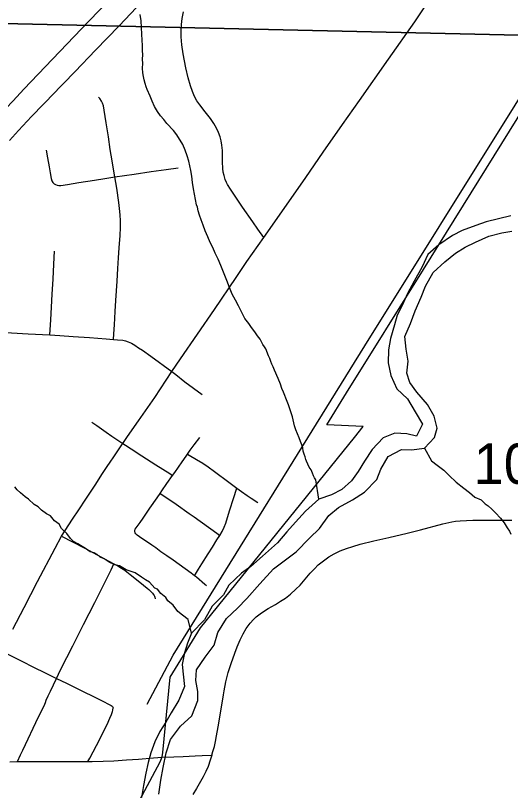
# Model space of a CAD drawing. Extents: x -8.8 to 41.4, y 0 to 34.6.
# Drawn here: x 2.435 to 2.947, y 16.815 to 17.616 of the extents above; entities that cross this region are included whole.
import ezdxf

# ---------------------------------------------------------------- set-up
doc = ezdxf.new("R2010")
doc.units = 0
for name, color, linetype in [('GM_X_City_Street', 7, 'Continuous'), ('GM_X_Corporation', 7, 'Continuous'), ('GM_X_County_Road', 7, 'Continuous'), ('GM_X_Major_Lake', 7, 'Continuous'), ('GM_X_Minor_River', 7, 'Continuous'), ('GM_X_Rail_Line', 7, 'Continuous'), ('GM_X_State_Route', 7, 'Continuous'), ('GM_X_Township_Text', 7, 'Continuous'), ('GM_X_US_Route', 7, 'Continuous')]:
    doc.layers.add(name, color=color, linetype=linetype)

msp = doc.modelspace()

# ---------------------------------------------------------------- linework, layer by layer
at = {"layer": 'GM_X_City_Street'}
for points in [[(2.43223, 16.98123), (2.4438, 17.00368), (2.45783, 17.03052), (2.47584, 17.06495), (2.48261, 17.0774), (2.49387, 17.09493), (2.50055, 17.10482), (2.50774, 17.11569), (2.51726, 17.13021), (2.52499, 17.14224), (2.52914, 17.14842), (2.5337, 17.15504), (2.53611, 17.15862), (2.53809, 17.16174), (2.54089, 17.16579), (2.54494, 17.17197), (2.54595, 17.17337), (2.54816, 17.17644), (2.55024, 17.17943), (2.5508, 17.18043), (2.56211, 17.19658), (2.57904, 17.22103), (2.59669, 17.2476), (2.60574, 17.26074), (2.64088, 17.31199), (2.66315, 17.34492), (2.67425, 17.36144), (2.69166, 17.38626), (2.7103, 17.41282), (2.73518, 17.44849), (2.75313, 17.47461), (2.77317, 17.50307), (2.79078, 17.5279), (2.82074, 17.57065), (2.84787, 17.6093), (2.85883, 17.62586)], [(2.69166, 17.38626), (2.68573, 17.39483), (2.68044, 17.40249), (2.66979, 17.41779), (2.66057, 17.43106), (2.6572, 17.43628), (2.65434, 17.44107), (2.65321, 17.44328), (2.65194, 17.4461), (2.65061, 17.45023), (2.64981, 17.45386), (2.64934, 17.45756), (2.64904, 17.46439), (2.64889, 17.47619), (2.64844, 17.48177), (2.64774, 17.48606), (2.64667, 17.49027), (2.645, 17.49495), (2.64289, 17.49945), (2.6401, 17.5043), (2.63661, 17.50944), (2.63126, 17.5163), (2.62546, 17.52361), (2.62265, 17.5277), (2.6202, 17.53202), (2.6179, 17.53711), (2.61587, 17.54298), (2.61356, 17.55137), (2.61123, 17.56167), (2.60835, 17.57631), (2.60704, 17.58554), (2.60632, 17.59359), (2.60615, 17.60042), (2.60648, 17.60662), (2.60725, 17.61278), (2.60854, 17.6195)], [(2.5364, 17.28088), (2.5367, 17.28674), (2.53718, 17.29602), (2.53807, 17.30965), (2.53883, 17.32129), (2.54012, 17.34117), (2.54083, 17.35415), (2.54155, 17.3654), (2.5422, 17.37546), (2.54304, 17.38843), (2.54352, 17.39656), (2.54359, 17.40344), (2.54325, 17.40956), (2.54255, 17.41644), (2.54166, 17.42246), (2.53962, 17.43719), (2.5377, 17.44906), (2.53395, 17.47125), (2.53297, 17.47736), (2.53108, 17.49022), (2.53047, 17.49445), (2.52883, 17.50482), (2.52667, 17.51797), (2.52584, 17.52239), (2.52506, 17.52504), (2.52405, 17.52715), (2.52203, 17.53008), (2.52088, 17.53136)], [(2.46677, 17.47671), (2.46818, 17.46857), (2.46976, 17.45952), (2.47085, 17.45325), (2.4719, 17.44722), (2.47263, 17.44486), (2.47355, 17.44327), (2.47481, 17.44192), (2.47639, 17.44099), (2.47813, 17.44043), (2.47992, 17.44016), (2.48173, 17.44016), (2.48881, 17.44108), (2.50045, 17.44313), (2.51663, 17.44566), (2.52723, 17.44737), (2.5377, 17.44906), (2.5577, 17.4519), (2.57527, 17.45441), (2.59069, 17.4566), (2.6033, 17.4584)], [(2.47057, 17.2855), (2.47142, 17.30121), (2.47236, 17.31419), (2.47305, 17.32782), (2.47393, 17.34328), (2.4747, 17.3586), (2.47538, 17.37231)], [(2.41961, 17.28827), (2.44798, 17.28673), (2.47057, 17.2855), (2.48084, 17.28491), (2.49466, 17.28386), (2.51139, 17.28282), (2.52874, 17.28147), (2.5364, 17.28088), (2.54061, 17.28063), (2.54583, 17.28003), (2.54873, 17.27942), (2.55141, 17.27858), (2.5548, 17.27712), (2.55832, 17.27506), (2.56227, 17.27238), (2.56619, 17.26972), (2.57474, 17.26374), (2.59669, 17.2476), (2.60061, 17.24471), (2.60998, 17.23707), (2.62816, 17.22401)], [(2.51374, 17.19554), (2.51916, 17.19176), (2.52881, 17.185), (2.53472, 17.18104), (2.54595, 17.17337), (2.54879, 17.17155), (2.55474, 17.16772), (2.56567, 17.1607), (2.58021, 17.15136), (2.5945, 17.14218), (2.59744, 17.14029)], [(2.63246, 17.02607), (2.63059, 17.02769), (2.62213, 17.03498), (2.62004, 17.03662), (2.61677, 17.0392), (2.59809, 17.05255), (2.5915, 17.0572), (2.58539, 17.06145), (2.57993, 17.06547), (2.5759, 17.06836), (2.56318, 17.07686), (2.56061, 17.07862), (2.55931, 17.07996), (2.55869, 17.08101), (2.55838, 17.08219), (2.55841, 17.08342), (2.55874, 17.08461), (2.55961, 17.08626), (2.56371, 17.09174), (2.567, 17.09626), (2.57396, 17.10654), (2.58129, 17.11711), (2.58447, 17.12179), (2.58614, 17.12423), (2.59143, 17.13186), (2.59744, 17.14029), (2.59972, 17.1435), (2.60714, 17.15422), (2.61141, 17.16029), (2.61286, 17.1624), (2.61568, 17.16637), (2.61955, 17.1718), (2.62542, 17.17964)], [(2.61286, 17.1624), (2.61463, 17.16134), (2.62221, 17.1568), (2.62856, 17.15295), (2.63418, 17.14909), (2.64075, 17.14444), (2.65567, 17.13343), (2.66397, 17.12699), (2.66852, 17.12383), (2.67465, 17.11957), (2.67872, 17.11674), (2.68539, 17.11229)], [(2.62004, 17.03662), (2.62429, 17.0434), (2.62778, 17.04899), (2.63412, 17.05911), (2.63855, 17.06621), (2.64331, 17.0738), (2.64615, 17.07835), (2.64862, 17.08242), (2.65087, 17.08683), (2.65249, 17.09086), (2.65412, 17.09684), (2.65646, 17.10483), (2.66026, 17.11634), (2.66397, 17.12699)], [(2.58447, 17.12179), (2.58822, 17.11922), (2.60095, 17.1105), (2.61459, 17.10097), (2.61968, 17.09748), (2.64329, 17.0805), (2.64615, 17.07835)], [(2.48261, 17.0774), (2.49377, 17.07162), (2.50656, 17.06498), (2.51503, 17.06057), (2.52387, 17.05592), (2.53094, 17.05213), (2.53673, 17.04903), (2.54093, 17.04673), (2.54448, 17.04455), (2.5479, 17.04221), (2.55019, 17.04051), (2.55366, 17.03792), (2.56363, 17.03004), (2.57125, 17.02382), (2.57274, 17.02247), (2.57481, 17.0204), (2.5765, 17.01867), (2.57742, 17.01754), (2.57821, 17.0163), (2.57867, 17.0154), (2.57899, 17.01444), (2.57932, 17.01278)], [(2.437, 16.84438), (2.44012, 16.85133), (2.44241, 16.85643), (2.45865, 16.89065), (2.46448, 16.90227), (2.46591, 16.90567), (2.46681, 16.90794), (2.46883, 16.91244), (2.47122, 16.91743), (2.47739, 16.93051), (2.48149, 16.93919), (2.48788, 16.95193), (2.49424, 16.964), (2.50524, 16.98628), (2.51692, 17.00892), (2.52576, 17.02603), (2.53378, 17.04285), (2.53673, 17.04903)], [(2.42092, 16.95841), (2.42759, 16.9551), (2.43593, 16.95097), (2.44279, 16.94757), (2.45218, 16.94294), (2.46709, 16.93558), (2.47739, 16.93051), (2.48775, 16.9254), (2.50349, 16.91763), (2.51701, 16.91094), (2.52458, 16.9072), (2.53263, 16.90312), (2.53386, 16.90241), (2.53478, 16.90177), (2.53528, 16.90127), (2.53598, 16.9)], [(2.50988, 16.84448), (2.51168, 16.84789), (2.51857, 16.86102), (2.52963, 16.88294), (2.5324, 16.88926), (2.53414, 16.89325), (2.53533, 16.89624), (2.53577, 16.89759), (2.53598, 16.9)]]:
    msp.add_lwpolyline(points, dxfattribs=at)
at = {"layer": 'GM_X_Corporation'}
for points in [[(2.36341, 18.68599), (3.3405, 18.67291), (3.35337, 18.6726), (3.33653, 17.58688), (2.37595, 17.60863)], [(2.37595, 17.60863), (3.33653, 17.58688), (3.32694, 16.59683), (2.35425, 16.60371)]]:
    msp.add_lwpolyline(points, close=True, dxfattribs=at)
for points in [[(2.55005, 16.77968), (2.58441, 16.84415), (2.58647, 16.84942), (2.5874, 16.85382), (2.59486, 16.93175), (2.62635, 16.98275), (2.78545, 17.17966), (2.7946, 17.19099), (2.75682, 17.19274), (2.77742, 17.22583), (2.85675, 17.3532), (3.0111, 17.60104), (3.28055, 18.03435)], [(2.58363, 17.64937), (2.54201, 17.60513), (2.51786, 17.58008), (2.49655, 17.55785), (2.47175, 17.53225), (2.46757, 17.52791), (2.46379, 17.52398), (2.45161, 17.51135), (2.43813, 17.49706), (2.42871, 17.48664)]]:
    msp.add_lwpolyline(points, dxfattribs=at)
at = {"layer": 'GM_X_County_Road'}
for p, q in [((2.42901, 16.84437), (2.437, 16.84438)), ((2.50583, 16.84447), (2.50988, 16.84448))]:
    msp.add_line(p, q, dxfattribs=at)
for points in [[(2.58671, 16.84889), (2.59874, 16.84945), (2.60847, 16.84989), (2.62071, 16.85045), (2.62811, 16.8508), (2.63787, 16.85124)], [(2.63787, 16.85124), (2.63637, 16.84604), (2.6341, 16.83931), (2.63188, 16.83417), (2.62916, 16.82886), (2.62209, 16.81658), (2.61838, 16.81032)], [(2.437, 16.84438), (2.44547, 16.84439), (2.46033, 16.84441), (2.48199, 16.84444), (2.50178, 16.84446), (2.50583, 16.84447)], [(2.50988, 16.84448), (2.51434, 16.84448), (2.52564, 16.84494), (2.53661, 16.84539), (2.54986, 16.84627), (2.56228, 16.84709), (2.57765, 16.84822), (2.58671, 16.84889)]]:
    msp.add_lwpolyline(points, dxfattribs=at)
at = {"layer": 'GM_X_Major_Lake'}
for points in [[(2.94702, 17.40861), (2.9218, 17.40255), (2.91106, 17.39871), (2.89686, 17.39345), (2.88685, 17.38844), (2.87289, 17.37862), (2.86121, 17.36873), (2.85551, 17.35599), (2.84708, 17.34106), (2.84024, 17.32836), (2.83493, 17.31599), (2.82969, 17.3059), (2.82673, 17.29612), (2.82288, 17.28181), (2.82062, 17.27011), (2.82021, 17.25683), (2.82321, 17.24345), (2.82924, 17.22997), (2.84029, 17.21938), (2.84823, 17.20622), (2.8558, 17.19346), (2.84972, 17.18074), (2.83956, 17.18333), (2.82707, 17.18409), (2.81516, 17.17914), (2.80378, 17.16696), (2.79583, 17.15506), (2.78943, 17.14424), (2.7823, 17.13459), (2.77255, 17.12578), (2.76176, 17.12041), (2.74873, 17.11588), (2.73469, 17.1034), (2.72448, 17.09194), (2.71545, 17.08197), (2.70599, 17.07049), (2.6904, 17.05692), (2.67831, 17.04628), (2.66862, 17.03936), (2.65572, 17.02685), (2.6501, 17.01677), (2.63835, 17.00498), (2.63034, 16.99118), (2.61702, 16.97716), (2.61291, 16.96703), (2.60956, 16.95688), (2.60729, 16.94481), (2.6085, 16.93489), (2.60962, 16.92195), (2.60388, 16.90808), (2.5959, 16.89503), (2.59029, 16.88533), (2.5843, 16.87564), (2.57903, 16.86479), (2.57489, 16.85353), (2.5723, 16.84336), (2.56969, 16.83242), (2.5674, 16.81958), (2.56513, 16.8075)], [(2.58306, 16.81075), (2.5854, 16.8251), (2.5877, 16.83833), (2.59082, 16.85342), (2.59542, 16.86733), (2.60571, 16.88106), (2.61741, 16.89171), (2.62359, 16.90747), (2.6235, 16.91696), (2.62158, 16.92842), (2.6223, 16.93941), (2.63104, 16.95243), (2.64052, 16.96467), (2.64434, 16.97784), (2.65313, 16.99238), (2.66446, 17.00304), (2.67425, 17.01299), (2.68761, 17.02815), (2.70175, 17.04366), (2.71263, 17.05206), (2.72504, 17.06117), (2.73914, 17.07554), (2.74931, 17.08548), (2.75882, 17.09886), (2.76895, 17.10728), (2.7836, 17.11519), (2.79598, 17.12316), (2.80852, 17.13606), (2.81265, 17.14695), (2.82026, 17.16), (2.83413, 17.16717), (2.84436, 17.16685), (2.85806, 17.16833), (2.86826, 17.17941), (2.87084, 17.1892), (2.86781, 17.20145), (2.86098, 17.21381), (2.84999, 17.2263), (2.84271, 17.23639), (2.8396, 17.24598), (2.84112, 17.25847), (2.83884, 17.27069), (2.83774, 17.28401), (2.84346, 17.29751), (2.84842, 17.31064), (2.85453, 17.3245), (2.85906, 17.33614), (2.8667, 17.34995), (2.8788, 17.36097), (2.89008, 17.37012), (2.90013, 17.37626), (2.91053, 17.38163), (2.92437, 17.38767), (2.93775, 17.39105), (2.94805, 17.39301)]]:
    msp.add_lwpolyline(points, dxfattribs=at)
at = {"layer": 'GM_X_Minor_River'}
for points in [[(2.74873, 17.11588), (2.74548, 17.13564), (2.74405, 17.13798), (2.74299, 17.13992), (2.74195, 17.14262), (2.74057, 17.1461), (2.73878, 17.14882), (2.73599, 17.15502), (2.73531, 17.15694), (2.73465, 17.15963), (2.73362, 17.16233), (2.7326, 17.16541), (2.73198, 17.16886), (2.73096, 17.17194), (2.72958, 17.17541), (2.72822, 17.17927), (2.72647, 17.18314), (2.72474, 17.18738), (2.72339, 17.19162), (2.72148, 17.20081), (2.71878, 17.20928), (2.71741, 17.21314), (2.71465, 17.22009), (2.71361, 17.22279), (2.71223, 17.22626), (2.71049, 17.23013), (2.70915, 17.23474), (2.70672, 17.24054), (2.70288, 17.24905), (2.7015, 17.25253), (2.70009, 17.25524), (2.69906, 17.25795), (2.69804, 17.26103), (2.69664, 17.26412), (2.69388, 17.27107), (2.69245, 17.27341), (2.69065, 17.27576), (2.68924, 17.27848), (2.68782, 17.28119), (2.6853, 17.28471), (2.68242, 17.28863), (2.67918, 17.29331), (2.6763, 17.29723), (2.6734, 17.30076), (2.67196, 17.30272), (2.66986, 17.30736), (2.6681, 17.31085), (2.66563, 17.31551), (2.66244, 17.32134), (2.65889, 17.32756), (2.65612, 17.33451), (2.65338, 17.34184), (2.64715, 17.35729), (2.64437, 17.36385), (2.64158, 17.37005), (2.63915, 17.37584), (2.63633, 17.38128), (2.6339, 17.38707), (2.63111, 17.39326), (2.62906, 17.39904), (2.62699, 17.40445), (2.62529, 17.40946), (2.62394, 17.41369), (2.62334, 17.41751), (2.6223, 17.42021), (2.62007, 17.43094), (2.61916, 17.43668), (2.6179, 17.44319), (2.6174, 17.44967), (2.61611, 17.45542), (2.61423, 17.46538), (2.61255, 17.47076), (2.6105, 17.47655), (2.60807, 17.48234), (2.60163, 17.49248), (2.59838, 17.49679), (2.59146, 17.50428), (2.58819, 17.50821), (2.58493, 17.51214), (2.58168, 17.51645), (2.57886, 17.52188), (2.57641, 17.5273), (2.57433, 17.53232), (2.57119, 17.53928), (2.57016, 17.54199), (2.56916, 17.54545), (2.56817, 17.54928), (2.56717, 17.55274), (2.56656, 17.55657), (2.56638, 17.56152), (2.56656, 17.56607), (2.56637, 17.57064), (2.56655, 17.57519), (2.56635, 17.57976), (2.56617, 17.58471), (2.56602, 17.59041), (2.5655, 17.59651), (2.5654, 17.60336), (2.56492, 17.61022), (2.56403, 17.61671)], [(2.85806, 17.16833), (2.86531, 17.15552), (2.87085, 17.15077), (2.87789, 17.14558), (2.8834, 17.14007), (2.89077, 17.13335), (2.89853, 17.12701), (2.90446, 17.12262), (2.90999, 17.11787), (2.91636, 17.11499), (2.92078, 17.11103), (2.92375, 17.10903), (2.92743, 17.10548), (2.93148, 17.10154), (2.9366, 17.09604), (2.94024, 17.09135), (2.94349, 17.0863), (2.94564, 17.08281), (2.94706, 17.07972)], [(2.61702, 16.97716), (2.61351, 16.99143), (2.60758, 16.99581), (2.60277, 16.99978), (2.59805, 17.00602), (2.59251, 17.01078), (2.59036, 17.01427), (2.58517, 17.01825), (2.5819, 17.02255), (2.5789, 17.02379), (2.57342, 17.03006), (2.56932, 17.03248), (2.56524, 17.03528), (2.55855, 17.0397), (2.55441, 17.04098), (2.54953, 17.04267), (2.54245, 17.04672), (2.53755, 17.04803), (2.53193, 17.0505), (2.52674, 17.0541), (2.52261, 17.05577), (2.51929, 17.05854), (2.51631, 17.06017), (2.51217, 17.06145), (2.50734, 17.06466), (2.50399, 17.06668), (2.49952, 17.06949), (2.49505, 17.07193), (2.49174, 17.07508), (2.48811, 17.08015), (2.48259, 17.08528), (2.48009, 17.08993), (2.47527, 17.09352), (2.47127, 17.0986), (2.46716, 17.10064), (2.46196, 17.10424), (2.45828, 17.10779), (2.45419, 17.11021), (2.4483, 17.11574), (2.44496, 17.11813), (2.44017, 17.12248), (2.43685, 17.12525), (2.43429, 17.12838)]]:
    msp.add_lwpolyline(points, dxfattribs=at)
at = {"layer": 'GM_X_Rail_Line'}
msp.add_lwpolyline([(2.57116, 16.90399), (2.59813, 16.95461), (2.79608, 17.27414), (3.10727, 17.77216), (3.34288, 18.15157), (3.39796, 18.23981), (3.43473, 18.29166)], dxfattribs=at)
at = {"layer": 'GM_X_State_Route'}
for p, q in [((2.42901, 16.84437), (2.437, 16.84438)), ((2.50583, 16.84447), (2.50988, 16.84448))]:
    msp.add_line(p, q, dxfattribs=at)
for points in [[(2.63787, 16.85124), (2.63911, 16.85486), (2.64059, 16.86006), (2.64183, 16.86538), (2.64296, 16.87092), (2.64459, 16.88024), (2.64825, 16.90291), (2.64989, 16.91333), (2.65066, 16.9176), (2.65255, 16.92676), (2.65498, 16.93644), (2.65792, 16.94598), (2.66162, 16.95658), (2.66412, 16.96297), (2.66735, 16.97043), (2.67047, 16.97658), (2.67366, 16.98199), (2.67775, 16.98758), (2.68115, 16.99132), (2.68386, 16.99397), (2.68927, 16.99828), (2.69609, 17.00278), (2.70371, 17.00703), (2.70901, 17.0102), (2.71416, 17.01356), (2.71951, 17.01767), (2.72497, 17.02264), (2.72928, 17.02702), (2.73981, 17.03923), (2.74402, 17.04384), (2.74808, 17.04777), (2.75344, 17.05213), (2.75914, 17.05603), (2.76457, 17.05919), (2.77076, 17.06224), (2.77716, 17.06481), (2.78368, 17.067), (2.79151, 17.06919), (2.80542, 17.07254), (2.82116, 17.07614), (2.83988, 17.08048), (2.85367, 17.08395), (2.87702, 17.09022), (2.88613, 17.09227), (2.88984, 17.09291), (2.89482, 17.09352), (2.9079, 17.09404), (2.92095, 17.09401), (2.93027, 17.09402), (2.93959, 17.09394), (2.94829, 17.09391)], [(2.58671, 16.84889), (2.59874, 16.84945), (2.60847, 16.84989), (2.62071, 16.85045), (2.62811, 16.8508), (2.63787, 16.85124)], [(2.437, 16.84438), (2.44547, 16.84439), (2.46033, 16.84441), (2.48199, 16.84444), (2.50178, 16.84446), (2.50583, 16.84447)], [(2.50988, 16.84448), (2.51434, 16.84448), (2.52564, 16.84494), (2.53661, 16.84539), (2.54986, 16.84627), (2.56228, 16.84709), (2.57765, 16.84822), (2.58671, 16.84889)]]:
    msp.add_lwpolyline(points, dxfattribs=at)
at = {"layer": 'GM_X_US_Route'}
msp.add_lwpolyline([(2.30105, 17.35359), (2.30769, 17.36469), (2.32111, 17.38637), (2.33038, 17.40038), (2.34785, 17.42533), (2.36061, 17.44296), (2.37155, 17.4573), (2.38441, 17.4733), (2.39944, 17.49106), (2.41408, 17.50764), (2.42503, 17.51954), (2.43267, 17.52769), (2.44369, 17.53951), (2.5106, 17.60961), (2.55833, 17.65938)], dxfattribs=at)

# ---------------------------------------------------------------- texts
at = {"layer": 'GM_X_Township_Text'}
msp.add_text('10', height=0.041856, rotation=0.00001, dxfattribs=at).set_placement((2.90878, 17.1315))

doc.saveas('drawing.dxf')
